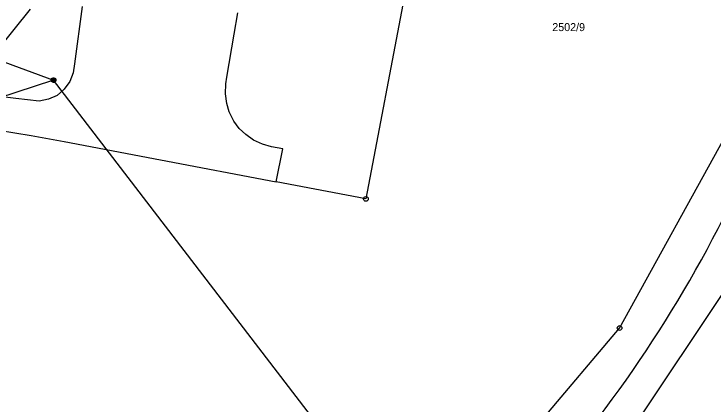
# Model space of a CAD drawing. Extents: x -468021 to -466942, y -1130484 to -1128584.
# Drawn here: x -467694.3 to -467545.8, y -1129913.1 to -1129830.2 of the extents above; entities that cross this region are included whole.
import ezdxf

# ---------------------------------------------------------------- set-up
doc = ezdxf.new("R2010")
doc.units = 0
doc.layers.add('DKM', color=7, linetype='Continuous')

msp = doc.modelspace()

# ---------------------------------------------------------------- linework, layer by layer
at = {"layer": 'DKM'}
for p, q in [((-467596.4, -1129747.27), (-467619.54, -1129869.5)), ((-467752.95, -1129819.79), (-467685.86, -1129844.26)), ((-467690.8, -1129829.19), (-467705.23, -1129847.01)), ((-467679.77, -1129828.6), (-467681.37, -1129840.81)), ((-467647.5, -1129834.51), (-467646.69, -1129829.95)), ((-467649.03, -1129843.65), (-467647.5, -1129834.51)), ((-467681.37, -1129840.81), (-467681.71, -1129842.71)), ((-467686.36, -1129844.16), (-467686.26, -1129843.96)), ((-467686.36, -1129844.36), (-467686.36, -1129844.16)), ((-467686.26, -1129843.96), (-467686.16, -1129843.86)), ((-467686.16, -1129843.86), (-467685.96, -1129843.76)), ((-467686.16, -1129844.06), (-467686.16, -1129844.46)), ((-467685.96, -1129843.76), (-467685.76, -1129843.76)), ((-467685.96, -1129844.56), (-467685.96, -1129843.96)), ((-467685.96, -1129843.96), (-467685.76, -1129843.96)), ((-467685.76, -1129843.76), (-467685.56, -1129843.86)), ((-467685.76, -1129843.96), (-467685.76, -1129844.56)), ((-467685.56, -1129843.86), (-467685.46, -1129843.96)), ((-467685.56, -1129844.46), (-467685.56, -1129844.06)), ((-467685.46, -1129843.96), (-467685.36, -1129844.16)), ((-467685.36, -1129844.16), (-467685.36, -1129844.36)), ((-467681.71, -1129842.71), (-467682.42, -1129844.58)), ((-467649.26, -1129845.08), (-467649.03, -1129843.65)), ((-467685.86, -1129844.26), (-467723.06, -1129856.48)), ((-467686.26, -1129844.56), (-467686.36, -1129844.36)), ((-467686.16, -1129844.66), (-467686.26, -1129844.56)), ((-467686.16, -1129844.46), (-467685.96, -1129844.56)), ((-467685.96, -1129844.76), (-467686.16, -1129844.66)), ((-467685.76, -1129844.76), (-467685.96, -1129844.76)), ((-467612.22, -1129940.32), (-467685.86, -1129844.26)), ((-467685.76, -1129844.56), (-467685.56, -1129844.46)), ((-467685.56, -1129844.66), (-467685.76, -1129844.76)), ((-467685.46, -1129844.56), (-467685.56, -1129844.66)), ((-467685.36, -1129844.36), (-467685.46, -1129844.56)), ((-467682.42, -1129844.58), (-467683.57, -1129846.22)), ((-467649.34, -1129847.2), (-467649.26, -1129845.08)), ((-467683.57, -1129846.22), (-467685.08, -1129847.56)), ((-467693.83, -1129848.17), (-467699.59, -1129847.46)), ((-467688.88, -1129848.71), (-467693.83, -1129848.17)), ((-467686.9, -1129848.35), (-467688.88, -1129848.71)), ((-467685.08, -1129847.56), (-467686.9, -1129848.35)), ((-467649.09, -1129849.21), (-467649.34, -1129847.2)), ((-467648.56, -1129851.04), (-467649.09, -1129849.21)), ((-467647.58, -1129852.98), (-467648.56, -1129851.04)), ((-467646.44, -1129854.51), (-467647.58, -1129852.98)), ((-467645.01, -1129855.85), (-467646.44, -1129854.51)), ((-467565.65, -1129896.92), (-467541.98, -1129853.93)), ((-467697.59, -1129854.92), (-467690.61, -1129856)), ((-467690.61, -1129856), (-467683.63, -1129857.29)), ((-467643.39, -1129857), (-467645.01, -1129855.85)), ((-467683.63, -1129857.29), (-467663.12, -1129861.2)), ((-467641.5, -1129857.86), (-467643.39, -1129857)), ((-467639.6, -1129858.42), (-467641.5, -1129857.86)), ((-467637.19, -1129858.89), (-467639.6, -1129858.42)), ((-467638.61, -1129865.89), (-467637.19, -1129858.89)), ((-467663.12, -1129861.2), (-467638.61, -1129865.89)), ((-467619.54, -1129869.5), (-467638.61, -1129865.89)), ((-467566.36, -1129923.5), (-467543.57, -1129889.4)), ((-467597.27, -1129934.35), (-467565.65, -1129896.92))]:
    msp.add_line(p, q, dxfattribs=at)
for centre, radius in [((-467619.54, -1129869.5), 0.5), ((-467619.54, -1129869.5), 0.01), ((-467565.65, -1129896.92), 0.5), ((-467565.65, -1129896.92), 0.01)]:
    msp.add_circle(centre, radius, dxfattribs=at)
msp.add_arc((-467786.16, -1129751.47), 271.53, 316.3122, 333.2904, dxfattribs=at)

# ---------------------------------------------------------------- texts
msp.add_text('2502/9', height=1.7, dxfattribs=at).set_placement((-467579.95, -1129833.86))

doc.saveas('drawing.dxf')
